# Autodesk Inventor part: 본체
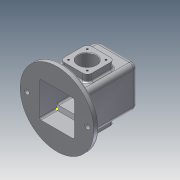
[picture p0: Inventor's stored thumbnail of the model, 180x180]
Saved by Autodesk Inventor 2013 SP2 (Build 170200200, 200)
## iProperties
Created: 2021-08
Part Number: 본체
Material: 알루미늄 6061
Document SubType Name: Modeling
Designer: kumcom17
Density: 2.71 g/cm^3
Mass: 882.571 g
Surface Area: 934.848 cm^2
Volume: 325.672 cm^3
Author: kumcom17
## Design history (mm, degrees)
sketch "스케치1"
  geometry: C1 r 67 at (0, 0); 1 further point
  constraints: 1 centre point, 1 coincident
  dimensions: "d0" = 134 diameter of C1
extrude "돌출1" new body sketch "스케치1" distance "d2" = 10; taper "d3" = 0 deg
sketch "스케치2"
  geometry: L1 (-37, 37)-(37, 37); L2 (37, 37)-(37, -37); L3 (37, -37)-(-37, -37); L4 (-37, -37)-(-37, 37); L5 (-37, 37)-(37, -37); L6 (37, 37)-(-37, -37); C1 r 67 at (0, 0) reference
  constraints: 12 end point, 2 midpoint, 2 parallel, 1 horizontal, 1 perpendicular
  dimensions: "d4" = 74 distance of L1.start L1.end; "d6" = 74 distance of L1.end L2.end
extrude "돌출2" join sketch "스케치2" distance "d7" = 100; taper "d8" = 0 deg
fillet "모깎기1" dims "d9" = 8
sketch "스케치3"
  geometry: C1 r 20 at (0, 0); 1 further point
  constraints: 1 centre point, 1 coincident
  dimensions: "d10" = 40 diameter of C1
extrude "돌출3" join sketch "스케치3" distance "d13" = 10; taper "d14" = -6 deg
sketch "스케치4"
  geometry: L1 (66, 0)-(66, 100) reference; L2 (29, 0)-(29, 100); L3 (-38, -10)-(96, -10) reference; L4 (-38, 45)-(96, 45); L5 (4, 70)-(54, 70); L6 (54, 70)-(54, 20); L7 (54, 20)-(4, 20); L8 (4, 20)-(4, 70); L9 (4, 70)-(54, 20); L10 (54, 70)-(4, 20); 2 further points
  constraints: 16 end point, 4 parallel, 3 midpoint, 1 horizontal, 1 perpendicular
  dimensions: "d15" = 37 distance between parallel lines of L1 L2; "d16" = 55 distance between parallel lines of L3 L4; "d17" = 50 distance of L5.start L5.end; "d18" = 50 distance of L5.end L6.end
extrude "돌출4" join sketch "스케치4" distance "d19" = 13; taper "d20" = 0 deg
fillet "모깎기2" dims "d21" = 8
hole "구멍1" diameter "d24" = 28; stored, may be unused: countersink angle "d28" = 90 deg, drill point angle "d30" = 0 deg; dims "d22" = 10, "d23" = 10, "d25" = 6, "d26" = 4, "d27" = 2, "d29" = 4
sketch "스케치5"
  geometry: L1 (42, 42)-(42, 8) reference; C1 r 16 at (17, 25); 1 further point
  constraints: 1 centre point
  dimensions: "d31" = 32 diameter of C1
extrude "돌출5" cut sketch "스케치5" stored distance "d33" = 13; taper "d34" = 0 deg
sketch "스케치7"
  geometry: 1 further point
sketch "스케치8"
  geometry: L1 (0, 0)-(0, -32); L2 (0, -32)-(30, -32); L3 (30, -32)-(32.548, -25); L4 (57.548, -25)-(57.548, 0); L5 (0, 0)-(0, 32); L6 (0, 32)-(30, 32); L7 (30, 32)-(32.548, 25); L8 (110, 37)-(110, 29) reference; L9 (80, 32)-(105, 32); L10 (110, -29)-(110, -37) reference; L11 (99.904, 0)-(30, 0); L12 (110, -37)-(10, -37) reference; L13 (105, -32)-(80, -32); L14 (57.548, 25)-(57.548, -25); L15 (32.548, 25)-(77.452, 25); L16 (80, 32)-(77.452, 25); L17 (32.548, -25)-(77.452, -25); L18 (80, -32)-(77.452, -25); L19 (105, 32)-(105, -32)
  constraints: 32 end point, 4 perpendicular, 3 parallel, 1 collinear, 1 symmetric about line, 1 vertical
  dimensions: "d43" = 32 distance of L1.start L1.end; "d44" = 30 distance of L1.end L2.end; "d46" = 110 deg angle of L2 L3; "d47" = 25 distance of L3.end L4.start; "d48" = 32 distance of L1.start L5.end; "d49" = 30 distance of L5.end L6.end; "d51" = 110 deg angle of L6 L7; "d94" = 50 distance of L6.end L9.start; "d95" = 50 distance of L2.end L13.end; "d96" = 110 deg angle of L9 L16
extrude "돌출6" cut sketch "스케치8" stored distance "d59" = 64; taper "d60" = 0 deg
hole "구멍2" diameter "d63" = 21; stored, may be unused: countersink angle "d67" = 90 deg, drill point angle "d69" = 0 deg; dims "d61" = 10, "d62" = 10, "d64" = 6, "d65" = 4, "d66" = 2, "d68" = 4
sketch "스케치9"
  geometry: A1 r 8 centre (0, 8) between (-8, 8) and (0, 0) reference; A2 r 8 centre (34, 8) between (34, 0) and (42, 8) reference; A3 r 8 centre (34, 42) between (42, 42) and (34, 50) reference; A4 r 8 centre (0, 42) between (0, 50) and (-8, 42) reference; 5 further points
  constraints: 4 coincident
hole "구멍3" sketch "스케치9" at (0, 42), (34, 42), (34, 8), (0, 8) diameter "d70" = 3.242; stored, may be unused: countersink angle "d74" = 90 deg, drill point angle "d76" = 118 deg; dims "d71" = 8, "d72" = 4, "d73" = 2, "d75" = 10
sketch "스케치10"
  geometry: A1 r 8 centre (12, 28) between (4, 28) and (12, 20) reference; A2 r 8 centre (46, 28) between (46, 20) and (54, 28) reference; A3 r 8 centre (46, 62) between (54, 62) and (46, 70) reference; A4 r 8 centre (12, 62) between (12, 70) and (4, 62) reference; 5 further points
  constraints: 4 coincident
hole "구멍4" sketch "스케치10" at (46, 62), (12, 62), (12, 28), (46, 28) diameter "d77" = 3.242; stored, may be unused: countersink angle "d81" = 90 deg, drill point angle "d83" = 118 deg; dims "d78" = 8, "d79" = 4, "d80" = 2, "d82" = 10
fillet "모깎기3" dims "d84" = 3
fillet "모깎기4" dims "d85" = 8
chamfer "모따기1" distance "d86" = 1; stored, may be unused: second distance "d87" = 2, angle "d88" = 45 deg
sketch "스케치11"
  geometry: 1 further point
fillet "모깎기5" dims "d89" = 3
sketch "스케치12"
  geometry: L1 (-8, 89)-(-8, 0) reference; L2 (10.051, 107)-(47.949, 107) reference; 2 further points
  constraints: 1 other
  dimensions: "d90" = 37 distance from line of L1 point (29, 79); "d91" = 28 distance from line of point (29, 79) L2
feature "엠보싱1" sketch "스케치12" dims "d92" = 0.5, "d93" = 0
fillet "모깎기6" dims "d98" = 3
fillet "모깎기7" dims "d99" = 3
sketch "스케치13"
  geometry: C1 r 64 at (0, 0) reference; A1 r 55 centre (0, 0) between (0, 55) and (0, -55); 3 further points
  constraints: 4 point on circle, 2 coincident, 1 centre point
  dimensions: "d100" = 110 diameter of A1
hole "구멍5" sketch "스케치13" at (-55, 0), (55, 0) diameter "d102" = 9; stored, may be unused: countersink angle "d106" = 90 deg, drill point angle "d108" = 0 deg; dims "d103" = 8, "d104" = 4, "d105" = 2, "d107" = 10
node "솔리드1"
mirror "대칭1"
other parameters: "d39" = 7
